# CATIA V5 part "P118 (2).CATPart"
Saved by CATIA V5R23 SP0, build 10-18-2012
Part number: 05-LICP-T02-E-S13-P118 (2)
Definition: butee a aiguilles
Description: butee_a_aiguilles_ax_19_32_02
Bounding box of the stored display mesh (mm): x 0.791 to 2.792, y -14.3 to 14.3, z -14.3 to 14.3
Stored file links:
  C:\wamp\www\COURS\CONCEPTION GMP1\TITRE 02-SEMESTRE 2\03-TP7-PRESSE MECANIQUE\eleve\P118 (2).CATPart
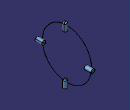
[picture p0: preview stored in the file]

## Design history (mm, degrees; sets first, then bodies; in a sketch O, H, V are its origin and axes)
Body1 (main body)
  Solid1: solid without history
